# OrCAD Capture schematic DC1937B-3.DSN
size C
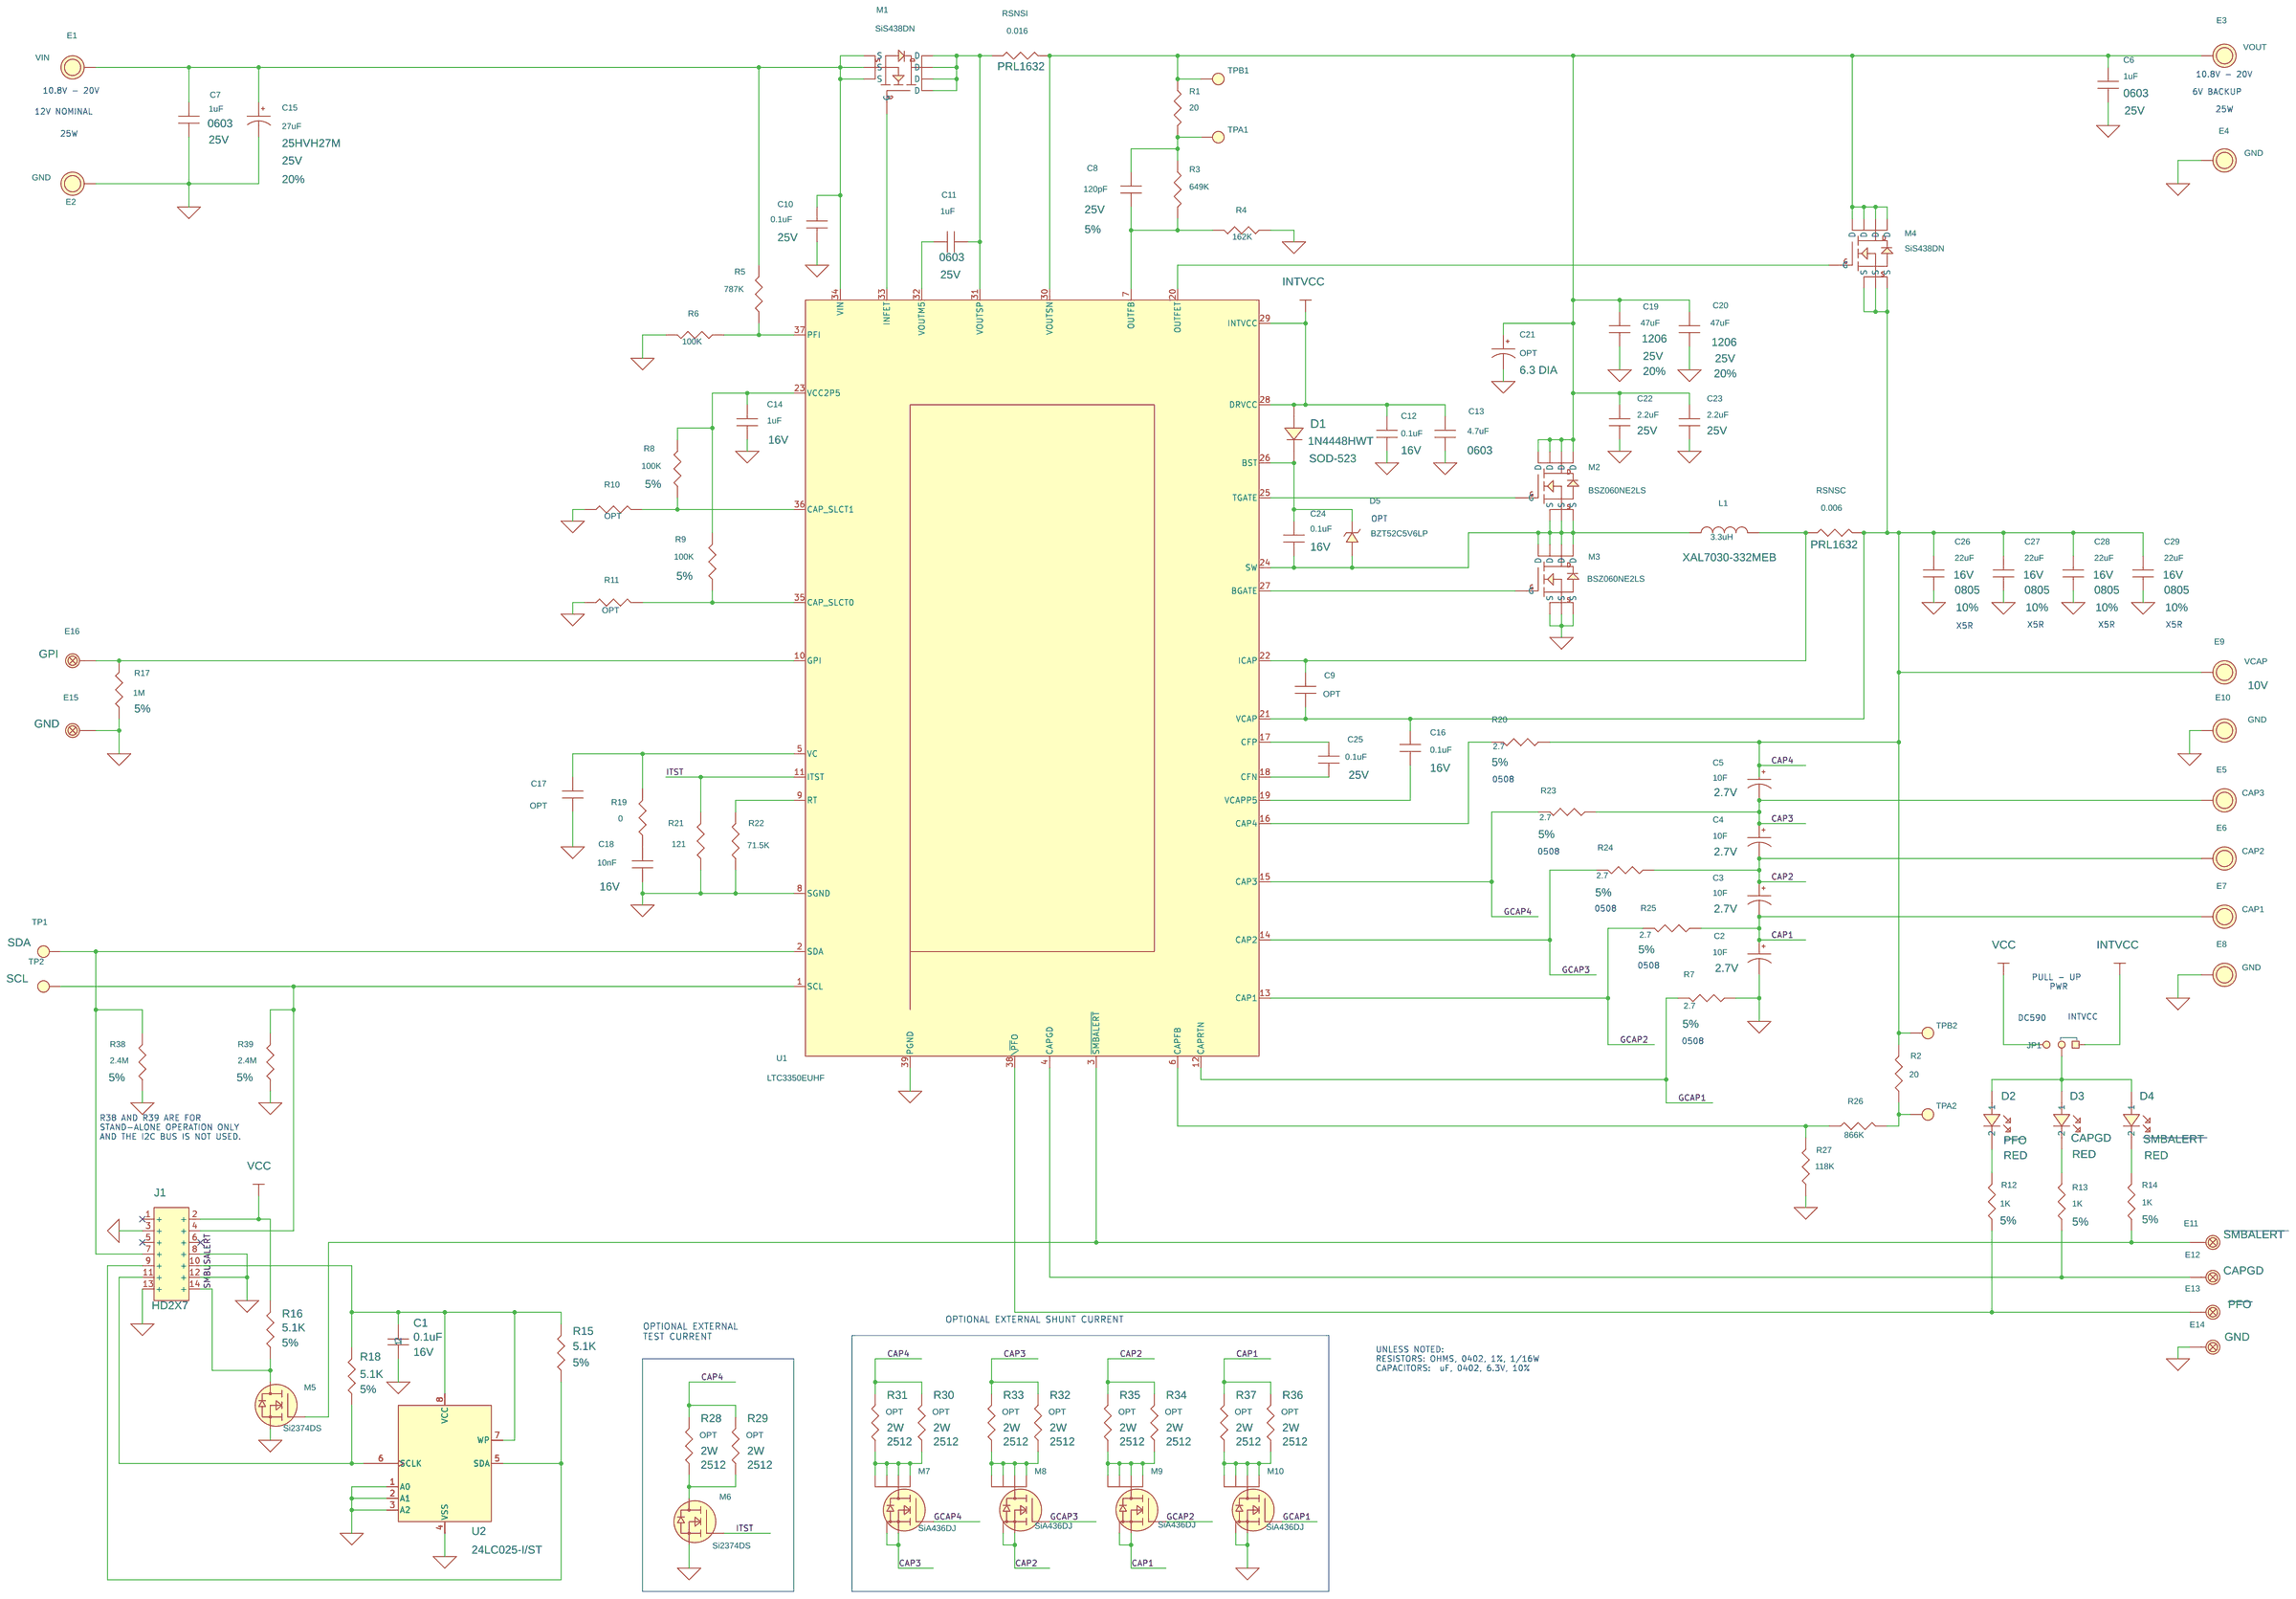
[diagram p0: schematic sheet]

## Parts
C1  0.1uF  [0402-SMALL]
C2  10F  [CAP-ESHSR-0010-0050C0-002R7]
C3  10F  [CAP-ESHSR-0010-0050C0-002R7]
C4  10F  [CAP-ESHSR-0010-0050C0-002R7]
C5  10F  [CAP-ESHSR-0010-0050C0-002R7]
C6  1uF  [0603]
C7  1uF  [0603]
C8  120pF  [0402-SMALL]
C9  OPT  [0402-SMALL]
C10  0.1uF  [0402-SMALL]
C11  1uF  [0603]
C12  0.1uF  [0402-SMALL]
C13  4.7uF  [0603]
C14  1uF  [0402-SMALL]
C15  27uF  [CAP-HVH-6.3X4.5]
C16  0.1uF  [0402-SMALL]
C17  OPT  [0402-SMALL]
C18  10nF  [0402-SMALL]
C19  47uF  [1206]
C20  47uF  [1206]
C21  OPT  [CAP-HVH-6.3X4.5]
C22  2.2uF  [0402-SMALL]
C23  2.2uF  [0402-SMALL]
C24  0.1uF  [0402-SMALL]
C25  0.1uF  [0402-SMALL]
C26  22uF  [0805]
C27  22uF  [0805]
C28  22uF  [0805]
C29  22uF  [0805]
D1  B0540WS  [SOD-523]
D2  PFO  [LNJ208R8ARA-RED-LED]
D3  CAPGD  [LITE-ON-GREEN-LED]
D4  SMBALERT  [LNJ208R8ARA-RED-LED]
D5  BZT52C5V6LP  [DIO-X1-DFN1006-2]
E1  VIN  [MILL-MAX-2501-2]
E2  GND  [MILL-MAX-2501-2]
E3  VOUT  [MILL-MAX-2501-2]
E4  GND  [MILL-MAX-2501-2]
E5  CAP3  [MILL-MAX-2501-2]
E6  CAP2  [MILL-MAX-2501-2]
E7  CAP1  [MILL-MAX-2501-2]
E8  GND  [MILL-MAX-2501-2]
E9  VCAP  [MILL-MAX-2501-2]
E10  GND  [MILL-MAX-2501-2]
E11  Testpoint  [MILL-MAX-2308]
E12  Testpoint  [MILL-MAX-2308]
E13  Testpoint  [MILL-MAX-2308]
E14  Testpoint  [MILL-MAX-2308]
E15  Testpoint  [MILL-MAX-2308]
E16  Testpoint  [MILL-MAX-2308]
J1  HD2X7  [HD2X7-079-MOLEX]
JP1  JP3X1/079\NO_1  [HD1X3-079]
L1  3.3uH  [IND-XAL7030]
M1  SiS438DN  [POWERPAK1212-8S]
M2  BSZ060NE2LS  [PG-TSDSON-8]
M3  BSZ060NE2LS  [PG-TSDSON-8]
M4  SiS438DN  [POWERPAK1212-8S]
M5  Si2374DS  [SOT23]
M6  Si2374DS  [SOT23-VISHAY]
M7  SiA436DJ  [POWERPAK-SC-70-6L-SINGLE]
M8  SiA436DJ  [POWERPAK-SC-70-6L-SINGLE]
M9  SiA436DJ  [POWERPAK-SC-70-6L-SINGLE]
M10  SiA436DJ  [POWERPAK-SC-70-6L-SINGLE]
R1  20  [0402-SMALL]
R2  20  [0402-SMALL]
R3  649K  [0402-SMALL]
R4  162K  [0402-SMALL]
R5  787K  [0402-SMALL]
R6  100K  [0402-SMALL]
R7  2.7  [LTR10-2012]
R8  100K  [0402-SMALL]
R9  100K  [0402-SMALL]
R10  OPT  [0402-SMALL]
R11  OPT  [0402-SMALL]
R12  1K  [0402-SMALL]
R13  1K  [0402-SMALL]
R14  1K  [0402-SMALL]
R15  5.1K  [0402-SMALL]
R16  5.1K  [0402-SMALL]
R17  1M  [0402-SMALL]
R18  5.1K  [0402-SMALL]
R19  0  [0402-SMALL]
R20  2.7  [LTR10-2012]
R21  121  [0402-SMALL]
R22  71.5K  [0402-SMALL]
R23  2.7  [LTR10-2012]
R24  2.7  [LTR10-2012]
R25  2.7  [LTR10-2012]
R26  866K  [0402-SMALL]
R27  118K  [0402-SMALL]
R28  OPT  [2512]
R29  OPT  [2512]
R30  OPT  [2512]
R31  OPT  [2512]
R32  OPT  [2512]
R33  OPT  [2512]
R34  OPT  [2512]
R35  OPT  [2512]
R36  OPT  [2512]
R37  OPT  [2512]
R38  2.4M  [0402-SMALL]
R39  2.4M  [0402-SMALL]
RSNSC  0.006  [1206-PRL1632]
RSNSI  0.016  [1206-PRL1632]
TP1  SDA  [PAD060/035]
TP2  SCL  [PAD.045D]
TPA1  OUTA  [PAD060/037]
TPA2  OUTA  [PAD060/037]
TPB1  OUTA  [PAD060/037]
TPB2  OUTA  [PAD060/037]
U1  LTC3350EUHF  [UHF_38]
U2  24LC025-I/ST  [TSSOP8]

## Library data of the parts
C1 = CAP_NP: 1st Part Field: 16V; 2nd Part Field: 10%; 3rd Part Field: X7R; 4th Part Field: MURATA; 5th Part Field: GRM155R71C104K; 6th Part Field: 0402; 7th Part Field: CAP.,
C2-C5 = CAPACITOR_POL: Part Num: ESHSR-0010-002R7; Volt: 2.7V
C6 C22 C23 = CAPACITOR: VOLTAGE: 25V
C7 C10 C25 = CAPACITOR: VOLT: 25V
C8 = CAPACITOR: TOL: 5%; VOLTAGE RATING: 25V
C9 C13 C17 = CAPACITOR
C11 = CAPACITOR: VOLTAGE RATING: 25V
C12 C16 C24 = CAPACITOR: VOLT: 16V
C14 C18 = CAPACITOR: VOLTAGE RATING: 16V
C15 = CAPACITOR_POL: PART NUMBER: 25HVH27M; TOL: 20%; VOLT: 25V
C19 C20 = CAPACITOR: TOL: 20%; VOLT: 25V
C21 = CAPACITOR_POL: PART NUMBER: 6.3 DIA
C26-C29 = CAPACITOR: TOLERANCE: 10%; VOLT: 16V
D1 = 1N4448HWT
D2 = LNJ208R8ARA_(RED-LED): 5TH PART FIELD: RED
D3 = LNJ208R8ARA_(RED-LED)_1: 5TH PART FIELD: RED
D4 = LNJ208R8ARA_(RED-LED)_2: 5TH PART FIELD: RED
D5 = DFLZ5V6
E1-E8 E10 = Large_Turret_2
E9 = Large_Turret_2: V-RANGE: 10V
E11 = mill-max-2308-2_2: 10th Part Field: SMBALERT
E12 = mill-max-2308-2_2: 10th Part Field: CAPGD
E13 = mill-max-2308-2_3: 10th Part Field: PFO
E14 = mill-max-2308-2_2: 9th Part Field: GND
E15 = mill-max-2308-2_2: 10th Part Field: GND
E16 = mill-max-2308-2_2: 9th Part Field: GPI
J1 = CON14AP_0
JP1 = JP3X1_079_NO_1
L1 = INDUCTOR: Alt Part Num: XAL7030-332MEB; Part Num: IHLP5050FDER4R7
M1-M3 = Si7850DP_1
M4 = Si7156DP_0
M5 = Si2308DS: BVDSS: 20V
M6 = Si2374DS_0: BVDSS: 20V
M7-M10 = SiA436DJ_2: BVDSS: 8V; VTH: 0.35~0.8V
R1-R6 R10 R11 R19 R21 R22 R26 R27 = RESISTOR_v2
R7 R20 R23-R25 = RESISTOR_v2: Tolerence: 5%
R8 R9 R12-R14 R38 R39 = RESISTOR_v2: TOL: 5%
R15 R16 R18 = RESISTOR: 1%: 1%; 1st Part Field: 1/8W; 2nd Part Field: 5%; 3rd Part Field: CHIP; 4th Part Field: PHILLIPS; 5th Part Field: 9C12063A51R0JM; 7th Part Field: RES.,
R17 = RESISTOR_v2: Tol: 5%
R28-R37 = RESISTOR_v2: Power: 2W
RSNSC = RESISTOR: PART#: PRL1632
RSNSI = RESISTOR: PRL1632: PRL1632
TP1 TP2 TPA1 TPA2 TPB1 TPB2 = T_POINT_R
U1 = 28Pin_Wide_Body_ZIF_25
U2 = LT1762_0

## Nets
GND_SIGNAL: C1.1 C2.2(-) C6.2 C7.2 C10.2 C12.1 C13.1 C14.2 C15.2(-) C17.2 C18.1 C19.2 C20.2 C21.2(-) C22.2 C23.2 C26.2 C27.2 C28.2 C29.2 E2.1 E4.1 E8.1 E10.1 E14.1(PIN) E15.1(PIN) J1.3(+) J1.8(+) J1.12(+) J1.13(+) M3.1(S) M3.2(S) M3.3(S) M5.2(S) M6.2(S) M10.4(S) M10.7(S) R4.1 R6.2 R7.1 R10.1 R11.1 R17.1 R21.1 R22.1 R27.1 R38.1 R39.1 U1.8(SGND) U1.39(PGND) U2.1(A0) U2.2(A1) U2.3(A2) U2.4(VSS)
VCC: J1.2(+) JP1.3 R16.2
CAP1: C2.1(+) C3.2(-) E7.1 M9.4(S) M9.7(S) R25.1 R36.2 R37.2
CAP2: C3.1(+) C4.2(-) E6.1 M8.4(S) M8.7(S) R24.1 R34.2 R35.2
CAP3: C4.1(+) C5.2(-) E5.1 M7.4(S) M7.7(S) R23.1 R32.2 R33.2
CAP4: C5.1(+) C9.1 C16.2 C26.1 C27.1 C28.1 C29.1 E9.1 M4.1(S) M4.2(S) M4.3(S) R2.2 R20.1 R28.2 R29.2 R30.2 R31.2 RSNSC.1 TPB2.1(TP) U1.21(VCAP)
GCAP1: M10.3(G) R7.2 U1.12(CAPRTN)
GCAP2: M9.3(G) R25.2 U1.13(CAP1)
GCAP3: M8.3(G) R24.2 U1.14(CAP2)
GCAP4: M7.3(G) R23.2 U1.15(CAP3)
INTVCC: C12.2 C13.2 D1.2(A) JP1.1 U1.28(DRVCC) U1.29(INTVCC)
ITST: M6.1(G) R21.2 U1.11(ITST)
SMBUSALERT: J1.14(+) M5.3(D) R16.1
N867205: C1.2 J1.10(+) R15.2 R18.2 U2.7(WP) U2.8(VCC)
N1202324: J1.11(+) R18.1 U2.6(SCLK)
N16567543: C7.1 C10.1 C15.1(+) E1.1 M1.1(S) M1.2(S) M1.3(S) R5.2 U1.34(VIN)
N16588589: C14.1 R8.2 R9.2 U1.23(VCC2P5)
N16601179: C11.1 M1.5(D) M1.6(D) M1.7(D) M1.8(D) RSNSI.2 U1.31(VOUTSP)
N16736151: J1.9(+) R15.1 U2.5(SDA)
N16778225: R5.1 R6.1 U1.37(PFI)
N16779519: M1.4(G) U1.33(INFET)
N16779910: C11.2 U1.32(VOUTM5)
N16781435: C24.2 D1.1(K) D5.1 U1.26(BST)
N16781593: C24.1 D5.2 L1.1 M2.1(S) M2.2(S) M2.3(S) M3.5(D) M3.6(D) M3.7(D) M3.8(D) U1.24(SW)
N16781788: C8.1 R3.2 R4.2 U1.7(OUTFB)
N16781856: C6.1 C19.1 C20.1 C21.1(+) C22.1 C23.1 E3.1 M2.5(D) M2.6(D) M2.7(D) M2.8(D) M4.5(D) M4.6(D) M4.7(D) M4.8(D) R1.1 RSNSI.1 TPB1.1(TP) U1.30(VOUTSN)
N16781919: M4.4(G) U1.20(OUTFET)
N16784218: C9.2 L1.2 RSNSC.2 U1.22(ICAP)
N16786835: C25.1 U1.18(CFN)
N16786900: C16.1 U1.19(VCAPP5)
N16787038: R20.2 U1.16(CAP4)
N16792735: J1.4(+) R39.2 TP2.1(TP) U1.1(SCL)
N16792850: J1.7(+) R38.2 TP1.1(TP) U1.2(SDA)
N16794015: D2.1 D3.1 D4.1 JP1.2
N16794056: D2.2 R12.2
N16794070: D3.2 R13.2
N16794084: D4.2 R14.2
N16794098: E11.1(PIN) M5.1(G) R14.1 U1.3(~{SMBALERT})
N16794151: E12.1(PIN) R13.1 U1.4(CAPGD)
N16794204: E13.1(PIN) R12.1 U1.38(\~{PF}O)
N16798947: C17.1 R19.2 U1.5(VC)
N16799513: R22.2 U1.9(RT)
N16802716: R8.1 R10.2 U1.36(CAP_SLCT1)
N16833148: E16.1(PIN) R17.2 U1.10(GPI)
N16834718: C25.2 U1.17(CFP)
N16854268: R2.1 R26.2 TPA2.1(TP)
N16855621: C8.2 R1.2 R3.1 TPA1.1(TP)
N16860509: R26.1 R27.2 U1.6(CAPFB)
N17005668: R9.1 R11.2 U1.35(CAP_SLCT0)
N17121194: M2.4(G) U1.25(TGATE)
N17551482: M3.4(G) U1.27(BGATE)
N17615082: M6.3(D) R28.1 R29.1
N17617319: M7.1(D) M7.2(D) M7.5(D) M7.6(D) R30.1 R31.1
N17630632: M8.1(D) M8.2(D) M8.5(D) M8.6(D) R32.1 R33.1
N17630710: M9.1(D) M9.2(D) M9.5(D) M9.6(D) R34.1 R35.1
N17631007: M10.1(D) M10.2(D) M10.5(D) M10.6(D) R36.1 R37.1
N17636917: C18.2 R19.1

Not connected (* = marked no-connect by the designer): J1 1(+)* 5(+)* 6(+)*

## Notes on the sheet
- 10.8V - 20V
- 10.8V - 20V
- 6V BACKUP
- 12V NOMINAL
- 25W
- 25W
- OPT
- X5R
- X5R
- X5R
- X5R
- 0508
- 0508
- 0508
- 0508
- PULL - UP
      PWR
- DC590
- INTVCC
- 0508
- R38 AND R39 ARE FOR
  STAND-ALONE OPERATION ONLY
  AND THE I2C BUS IS NOT USED.
- OPTIONAL EXTERNAL SHUNT CURRENT
- OPTIONAL EXTERNAL
  TEST CURRENT
- UNLESS NOTED:
  RESISTORS: OHMS, 0402, 1%, 1/16W
  CAPACITORS:  uF, 0402, 6.3V, 10%
